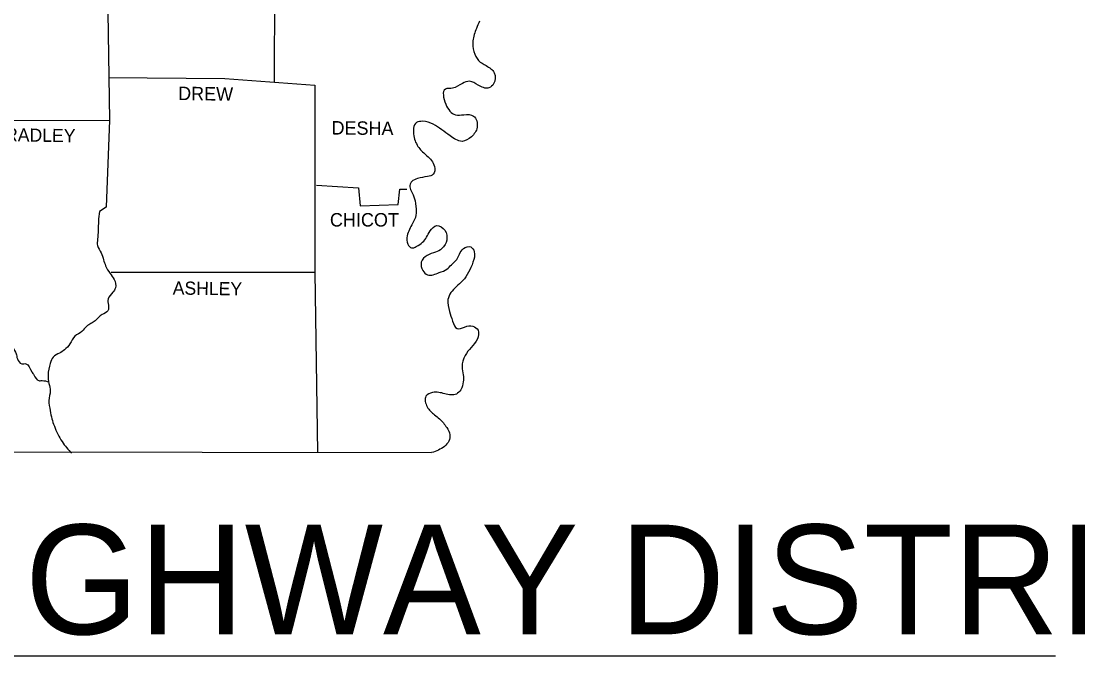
# Model space of a CAD drawing. Extents: x -33639 to 34530, y -17264 to 5867.
# Drawn here: x 2998 to 4855, y -10461 to -9345 of the extents above; entities that cross this region are included whole.
import ezdxf

# ---------------------------------------------------------------- set-up
doc = ezdxf.new("R2010")
doc.units = 0
doc.layers.add('1', color=7, linetype='Continuous')
doc.layers.add('2', color=7, linetype='Continuous')

msp = doc.modelspace()

# ---------------------------------------------------------------- linework, layer by layer
at = {"layer": '1'}
msp.add_line((1228.1, -10460.7), (4815.5, -10460.7), dxfattribs=at)
for points in [[(3160.4, -9221.3), (3161, -9290.1), (3149.4, -9290.6), (3152.7, -9519)], [(3532.5, -9250.4), (3525.9, -9265.3), (3496.7, -9268.1), (3495.1, -9287.9), (3442.8, -9287.9), (3442.2, -9452.4)], [(3151.1, -9444.2), (3355.3, -9445.8), (3513.8, -9457.9)], [(3513.8, -9457.9), (3513.8, -9787), (3518.2, -10103.5)], [(2904, -9519.6), (3152.7, -9519)], [(3152.7, -9519), (3147.2, -9672), (3135.1, -9679.7)], [(3516.5, -9633.5), (3590.3, -9637.9), (3593.6, -9669.8), (3660.2, -9667.6), (3662.9, -9640.6), (3675.6, -9640.6)], [(1700.9, -9655), (1702, -10100.2), (3719, -10103.5)], [(3156, -9786.5), (3513.8, -9786.5)]]:
    msp.add_lwpolyline(points, dxfattribs=at)
for points in [[(3803.3, -9345.1), (3797.7, -9357.8), (3791.7, -9379.8), (3793.3, -9398.5), (3801.6, -9414.4), (3814.8, -9423.3), (3829.1, -9435.9), (3828, -9455.2), (3819.8, -9462.3), (3800.5, -9457.4), (3785.6, -9450.8), (3773, -9454.6), (3755.9, -9462.9), (3743.3, -9464.5), (3743.8, -9490.9), (3760.9, -9509.7), (3775.7, -9509.7), (3792.8, -9511.9), (3798.9, -9531.7), (3788.9, -9548.2), (3772.4, -9556.4), (3751.5, -9546.5), (3736.7, -9536.1), (3721.8, -9526.2), (3703.1, -9521.2), (3692.6, -9523.4), (3687.7, -9546.5), (3696.5, -9567.4), (3710.8, -9581.8), (3724, -9600.5), (3721.8, -9614.2), (3711.9, -9618.1), (3694.3, -9621.9), (3683.8, -9627.4), (3681.1, -9631.8), (3686.6, -9650.6), (3691.5, -9670.9), (3691.5, -9686.3), (3685.5, -9700.6), (3676.1, -9722.6), (3677.2, -9737), (3683.8, -9743.6), (3692.1, -9741.4), (3703.1, -9733.7), (3710.2, -9724.8), (3716.3, -9713.8), (3727.9, -9704.5), (3742.2, -9712.7), (3745.5, -9729.8), (3737.2, -9744.7), (3725.7, -9751.3), (3711.3, -9756.8), (3700.9, -9768.9), (3703.6, -9783.2), (3711.9, -9790.9), (3732.3, -9787), (3746, -9781), (3753.7, -9773.3), (3763.1, -9763.9), (3768, -9754.6), (3775.2, -9744.7), (3787.8, -9741.9), (3793.9, -9750.2), (3791.7, -9768.9), (3784, -9786.5), (3773.5, -9801.3), (3762, -9811.8), (3747.7, -9834.4), (3750.4, -9855.3), (3755.9, -9872.3), (3763.6, -9885.6), (3776.8, -9882.8), (3791.7, -9881.1), (3800.5, -9888.3), (3799.4, -9903.7), (3788.4, -9918.6), (3777.9, -9932.9), (3772.4, -9952.7), (3774.6, -9966.5), (3774.6, -9979.1), (3770.2, -9992.9), (3762.5, -10000.6), (3742.2, -10000), (3720.7, -9997.8), (3709.1, -10004.4), (3711.3, -10023.1), (3724, -10036.9), (3732.8, -10044.1), (3745.5, -10059.5), (3751, -10072.1), (3749.3, -10083.1), (3741.6, -10092.5), (3719, -10103.5)], [(3135.1, -9679.7), (3133.5, -9696.8), (3132.9, -9712.7), (3131.8, -9728.2), (3131.8, -9739.7), (3138.4, -9752.4), (3142.3, -9764.5), (3146.1, -9774.9), (3153.8, -9788.7), (3161, -9799.1), (3163.2, -9814), (3158.8, -9821.7), (3150.5, -9833.3), (3150, -9854.2), (3140.1, -9860.8), (3127.4, -9871.8), (3120.3, -9876.7), (3112.6, -9881.7), (3104.3, -9890.5), (3092.2, -9898.8), (3083.4, -9912.5), (3073.5, -9923), (3065.2, -9928.5), (3053.7, -9935.6), (3048.7, -9946.6), (3044.9, -9967), (3046.5, -9981.9), (3048.7, -9995.1), (3046, -10011.6), (3048.7, -10029.7), (3051.5, -10044.1), (3055.9, -10056.7), (3061.9, -10071), (3069.6, -10084.2), (3086.1, -10104.6)], [(2586.4, -9806.9), (2595.2, -9800.8), (2603.5, -9797.5), (2611.7, -9799.1), (2620.5, -9800.2), (2628.2, -9799.1), (2638.2, -9800.8), (2646.4, -9805.8), (2655.8, -9809.6), (2665.1, -9809.6), (2673.4, -9809.6), (2680.5, -9814.6), (2693.7, -9814), (2704.7, -9809.6), (2715.8, -9806.3), (2730.6, -9804.6), (2743.8, -9814), (2753.2, -9821.7), (2760.9, -9830.5), (2766.4, -9840.4), (2772.4, -9845.9), (2782.3, -9849.8), (2790.1, -9851.4), (2799.4, -9854.2), (2804.4, -9856.4), (2808.8, -9866.8), (2815.9, -9881.1), (2829.7, -9886.1), (2846.7, -9879.5), (2860.5, -9875.6), (2870.4, -9872.3), (2876.5, -9870.1), (2882, -9869.6), (2880.3, -9868.5), (2886.9, -9866.8), (2893, -9871.2), (2896.8, -9877.3), (2903.4, -9886.1), (2909.5, -9893.8), (2915.5, -9896.6), (2921.6, -9893.3), (2929.8, -9896), (2937, -9898.8), (2945.3, -9901), (2952.4, -9901.5), (2961.8, -9903.7), (2968.9, -9907.6), (2975.5, -9911.4), (2982.1, -9918.6), (2988.7, -9929.6), (2990.9, -9938.4), (2998.6, -9947.2), (3005.8, -9947.2), (3016.2, -9961.5), (3020.1, -9967), (3028.4, -9976.9), (3034.4, -9976.9), (3046, -9979.1)]]:
    msp.add_spline(points, degree=3, dxfattribs=at)

# ---------------------------------------------------------------- texts
at = {"layer": '2'}
for s, height, rotation, p in [('DREW', 23.66, 359.2258, (3273.3, -9483.8)), ('DESHA', 23.66, 359.3704, (3542.9, -9544.3)), ('BRADLEY', 23.11, 359.1449, (2948.6, -9555.9)), ('ASHLEY', 23.11, 359.2361, (3263.9, -9825.6))]:
    msp.add_text(s, height=height, rotation=rotation, dxfattribs=at).set_placement(p)
for s, height, p in [('CHICOT', 23.67, (3540.2, -9706.1)), ('ARKANSAS HIGHWAY DISTRICT 1', 192.623, (1272.1, -10422.7))]:
    msp.add_text(s, height=height, dxfattribs=at).set_placement(p)

doc.saveas('drawing.dxf')
